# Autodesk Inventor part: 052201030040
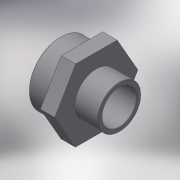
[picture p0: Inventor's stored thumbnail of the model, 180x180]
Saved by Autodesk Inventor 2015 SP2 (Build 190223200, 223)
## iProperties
Created: 2017-10
Part Number: 052201030040
Material: Generic
Description: PLASSON SOCKET NIPPLE THR. P 3"-4"
Document SubType Name: Modeling
Designer: KIM
Density: 1 g/cm^3
Appearance: Default
Author: KIM
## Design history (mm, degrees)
derived "052201.ipt"
feature "Solid1::052201.ipt"
tag "TaggingFeature1"
body "Solid1"
other parameters: "d0" = 87, "d13" = 0, "d14" = 1.10072, "d17" = 33, "d18" = 48, "d19" = 125.48208, "d20" = 110.072, "d21" = 87.884, "d22" = 26.4, "d23" = 104.5684, "d24" = 70.3072, "d26" = -33, "G_" = 110.072, "R_" = 87.884, "lt_1" = 33, "H_" = 87
